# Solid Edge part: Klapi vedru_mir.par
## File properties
Author: Türk
Template: Iso Part.par
Last saved by: Türk
Revision: 2
Application: Solid Edge
Density: 7833,000 kg/m^3
Accuracy: 0,990
Username: Türk
Material: Steel
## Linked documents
Klapi vedru.par
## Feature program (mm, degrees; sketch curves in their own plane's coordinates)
part copy "CopiedPart_1"
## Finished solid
Body 1: solid body, 3 faces, 2 edges, 0 vertices.
  Faces by surface: plane 2, spline 1
  Edges by curve: intersection 2
Bounding box of the edges (mm; curved faces can reach further): 17.000 x 19.333 x 18.336, from (0, -9.6665, -9.6664) to (17, 9.6667, 8.6699).
Planar faces by outward normal: +x 1, -x 1
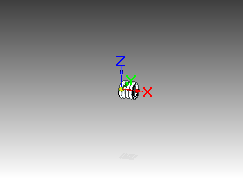
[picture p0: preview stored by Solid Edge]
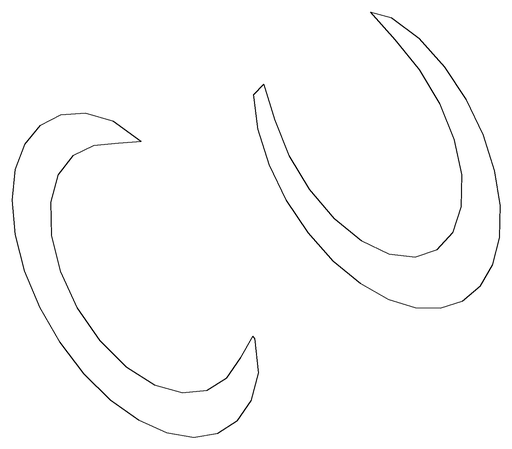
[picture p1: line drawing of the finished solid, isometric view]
